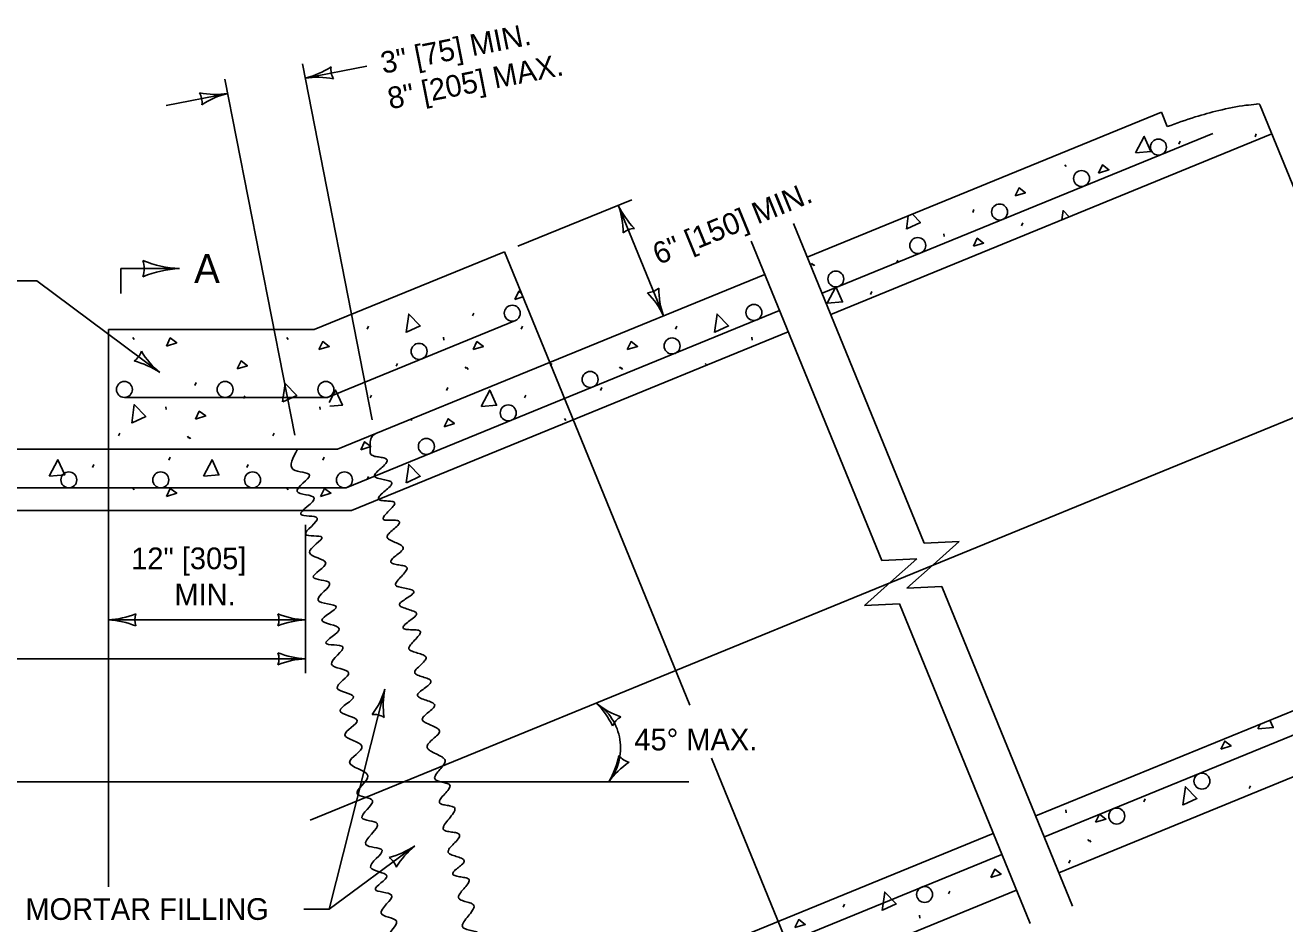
# Model space of a CAD drawing. Extents: x 49991.4 to 50021, y 49987.6 to 50011.4.
# Drawn here: x 50003.206 to 50006.69, y 50003.512 to 50005.996 of the extents above; entities that cross this region are included whole.
import ezdxf

# ---------------------------------------------------------------- set-up
doc = ezdxf.new("R2010")
doc.units = 0
for name, color, linetype in [('Level 1', 7, 'Continuous'), ('Level 2', 7, 'Continuous'), ('Level 3', 7, 'Continuous'), ('Level 4', 7, 'Continuous'), ('Level 5', 7, 'Continuous'), ('Level 6', 7, 'Continuous')]:
    doc.layers.add(name, color=color, linetype=linetype)

msp = doc.modelspace()

# ---------------------------------------------------------------- linework, layer by layer
at = {"layer": 'Level 1'}
for p, q in [((50006.6221, 50005.7743), (50007.2537, 50004.2304)), ((50005.3695, 50005.355), (50006.3487, 50005.7556)), ((50006.3487, 50005.7556), (50006.3651, 50005.7158)), ((50006.4914, 50005.6969), (50005.4104, 50005.255)), ((50005.4343, 50005.1964), (50006.6543, 50005.6955)), ((50006.3972, 50005.6675), (50006.4008, 50005.6755)), ((50006.6077, 50005.6879), (50006.6112, 50005.6959)), ((50006.0818, 50005.6106), (50006.0854, 50005.6053)), ((50005.827, 50005.4783), (50005.8305, 50005.4863)), ((50005.962, 50005.4419), (50005.9655, 50005.4499)), ((50005.7467, 50005.4196), (50005.7476, 50005.4116)), ((50004.0053, 50005.1544), (50004.5319, 50005.3698)), ((50004.5319, 50005.3698), (50004.6571, 50005.0636)), ((50005.3809, 50005.3379), (50005.3845, 50005.3326)), ((50005.3855, 50005.3359), (50005.3891, 50005.3305)), ((50005.6164, 50005.3389), (50005.6199, 50005.3469)), ((50004.0705, 50004.8236), (50005.2519, 50005.307)), ((50005.5445, 50005.2517), (50005.548, 50005.2596)), ((50005.2928, 50005.207), (50004.0941, 50004.7168)), ((50004.4434, 50005.1924), (50004.447, 50005.2004)), ((50003.4365, 50005.1544), (50003.4365, 50004.8236)), ((50003.4365, 50005.1544), (50004.0053, 50005.1544)), ((50004.562, 50005.1794), (50004.0422, 50004.9669)), ((50004.1091, 50004.6543), (50005.3168, 50005.1484)), ((50004.152, 50005.156), (50004.1556, 50005.164)), ((50004.5784, 50005.156), (50004.5819, 50005.164)), ((50005.0048, 50005.156), (50005.0083, 50005.164)), ((50003.5039, 50005.1323), (50003.5074, 50005.127)), ((50003.9303, 50005.1323), (50003.9338, 50005.127)), ((50004.3631, 50005.1337), (50004.364, 50005.1257)), ((50005.2159, 50005.1337), (50005.2168, 50005.1257)), ((50004.2328, 50005.053), (50004.2364, 50005.061)), ((50004.4237, 50005.052), (50004.4273, 50005.0467)), ((50004.4283, 50005.05), (50004.4319, 50005.0446)), ((50004.6592, 50005.053), (50004.6627, 50005.061)), ((50004.8501, 50005.052), (50004.8537, 50005.0467)), ((50004.8547, 50005.05), (50004.8582, 50005.0446)), ((50005.0876, 50005.0577), (50005.0891, 50005.061)), ((50003.6754, 50005), (50003.679, 50005.008)), ((50004.1609, 50004.9657), (50004.1644, 50004.9737)), ((50004.3713, 50004.9862), (50004.3749, 50004.9942)), ((50004.5873, 50004.9657), (50004.5908, 50004.9737)), ((50004.7977, 50004.9862), (50004.8013, 50004.9942)), ((50003.4807, 50004.9669), (50004.0422, 50004.9669)), ((50003.5951, 50004.9413), (50003.596, 50004.9333)), ((50003.8104, 50004.9636), (50003.8139, 50004.9716)), ((50004.0215, 50004.9413), (50004.0224, 50004.9333)), ((50004.2719, 50004.9089), (50004.2754, 50004.9036)), ((50004.6983, 50004.9089), (50004.7018, 50004.9036)), ((50003.4648, 50004.8606), (50003.4684, 50004.8686)), ((50003.8912, 50004.8606), (50003.8947, 50004.8686)), ((50003.6557, 50004.8596), (50003.6593, 50004.8543)), ((50003.6603, 50004.8576), (50003.6639, 50004.8522)), ((50002.7761, 50004.8236), (50004.0705, 50004.8236)), ((50003.6033, 50004.7938), (50003.6069, 50004.8018)), ((50004.0297, 50004.7938), (50004.0333, 50004.8018)), ((50003.3929, 50004.7733), (50003.3964, 50004.7813)), ((50003.8193, 50004.7733), (50003.8228, 50004.7813)), ((50004.152, 50004.7402), (50004.1556, 50004.7482)), ((50002.7761, 50004.7168), (50004.0941, 50004.7168)), ((50003.5039, 50004.7165), (50003.5074, 50004.7112)), ((50003.9303, 50004.7165), (50003.9338, 50004.7112)), ((50002.7761, 50004.6543), (50004.1091, 50004.6543)), ((50006.0014, 50003.8098), (50007.2216, 50004.3088)), ((50007.1297, 50004.2036), (50006.0252, 50003.7516)), ((50006.0656, 50003.6529), (50007.045, 50004.0536)), ((50006.5915, 50003.8854), (50006.595, 50003.8934)), ((50006.3001, 50003.849), (50006.3036, 50003.857)), ((50006.0848, 50003.8267), (50006.0857, 50003.8187)), ((50004.3994, 50003.1543), (50005.8839, 50003.7616)), ((50006.1454, 50003.745), (50006.149, 50003.7397)), ((50006.15, 50003.743), (50006.1536, 50003.7376)), ((50005.9077, 50003.7036), (50004.4541, 50003.109)), ((50006.093, 50003.6792), (50006.0966, 50003.6872)), ((50004.4328, 50002.985), (50005.9481, 50003.6048)), ((50005.7598, 50003.5942), (50005.7634, 50003.6022)), ((50005.4684, 50003.5578), (50005.472, 50003.5658)), ((50005.6796, 50003.5355), (50005.6804, 50003.5275))]:
    msp.add_line(p, q, dxfattribs=at)
for points in [[(50006.2773, 50005.6435), (50006.3013, 50005.6888), (50006.32, 50005.647), (50006.2782, 50005.6435)], [(50006.1751, 50005.5875), (50006.1857, 50005.6097), (50006.2035, 50005.5964), (50006.1751, 50005.5875)], [(50005.9444, 50005.5241), (50005.955, 50005.5463), (50005.9728, 50005.5329), (50005.9444, 50005.5241)], [(50005.6436, 50005.4327), (50005.6487, 50005.4692)], [(50005.66, 50005.4739), (50005.6825, 50005.4506), (50005.6444, 50005.433)], [(50006.0735, 50005.4579), (50006.077, 50005.4835), (50006.0938, 50005.4662)], [(50005.8288, 50005.3851), (50005.8394, 50005.4073), (50005.8572, 50005.394), (50005.8288, 50005.3851)], [(50004.5608, 50005.2382), (50004.5715, 50005.2604), (50004.5788, 50005.2548)], [(50005.4246, 50005.2277), (50005.4486, 50005.273), (50005.4672, 50005.2312), (50005.4255, 50005.2277)], [(50004.5829, 50005.245), (50004.5608, 50005.2382)], [(50004.26, 50005.1468), (50004.2671, 50005.1976), (50004.2989, 50005.1647), (50004.2609, 50005.1471)], [(50005.1128, 50005.1468), (50005.1198, 50005.1976), (50005.1516, 50005.1647), (50005.1136, 50005.1471)], [(50003.5971, 50005.1092), (50003.6078, 50005.1314), (50003.6255, 50005.1181), (50003.5971, 50005.1092)], [(50004.0188, 50005.0992), (50004.0295, 50005.1214), (50004.0472, 50005.1081), (50004.0188, 50005.0992)], [(50004.4452, 50005.0992), (50004.4558, 50005.1214), (50004.4736, 50005.1081), (50004.4452, 50005.0992)], [(50004.8716, 50005.0992), (50004.8822, 50005.1214), (50004.9, 50005.1081), (50004.8716, 50005.0992)], [(50003.7928, 50005.0458), (50003.8035, 50005.068), (50003.8212, 50005.0546), (50003.7928, 50005.0458)], [(50003.9184, 50004.9544), (50003.9255, 50005.0052), (50003.9573, 50004.9723), (50003.9192, 50004.9547)], [(50004.0471, 50004.9532), (50004.065, 50004.9871), (50004.0836, 50004.9453), (50004.0493, 50004.9424)], [(50004.4674, 50004.9418), (50004.4914, 50004.9871), (50004.51, 50004.9453), (50004.4683, 50004.9418)], [(50003.5011, 50004.8963), (50003.5082, 50004.9471), (50003.54, 50004.9142), (50003.502, 50004.8966)], [(50003.6772, 50004.9068), (50003.6878, 50004.929), (50003.7056, 50004.9157), (50003.6772, 50004.9068)], [(50004.3651, 50004.8858), (50004.3758, 50004.908), (50004.3935, 50004.8947), (50004.3651, 50004.8858)], [(50004.1344, 50004.8223), (50004.1451, 50004.8446), (50004.1628, 50004.8312), (50004.1344, 50004.8223)], [(50003.273, 50004.7494), (50003.297, 50004.7947), (50003.3156, 50004.7529), (50003.2739, 50004.7494)], [(50003.6994, 50004.7494), (50003.7234, 50004.7947), (50003.742, 50004.7529), (50003.7003, 50004.7494)], [(50004.26, 50004.731), (50004.2671, 50004.7818), (50004.2989, 50004.7489), (50004.2609, 50004.7313)], [(50003.5971, 50004.6934), (50003.6078, 50004.7156), (50003.6255, 50004.7023), (50003.5971, 50004.6934)], [(50004.0235, 50004.6934), (50004.0342, 50004.7156), (50004.0519, 50004.7023), (50004.0235, 50004.6934)], [(50006.6489, 50004.0746), (50006.6581, 50004.0541), (50006.6163, 50004.0506)], [(50006.6155, 50004.0506), (50006.6224, 50004.0637)], [(50006.5132, 50003.9946), (50006.5239, 50004.0168), (50006.5416, 50004.0035), (50006.5132, 50003.9946)], [(50006.4081, 50003.8398), (50006.4152, 50003.8906), (50006.447, 50003.8577), (50006.409, 50003.8401)], [(50006.1669, 50003.7922), (50006.1775, 50003.8144), (50006.1953, 50003.8011), (50006.1669, 50003.7922)], [(50005.8772, 50003.64), (50005.8879, 50003.6622), (50005.9056, 50003.6489), (50005.8772, 50003.64)], [(50005.5765, 50003.5486), (50005.5835, 50003.5994), (50005.6153, 50003.5665), (50005.5773, 50003.5489)], [(50005.3352, 50003.501), (50005.3459, 50003.5232), (50005.3636, 50003.5099), (50005.3352, 50003.501)]]:
    msp.add_lwpolyline(points, dxfattribs=at)
for centre in [(50006.3406, 50005.6592), (50006.1279, 50005.5723), (50005.9014, 50005.4797), (50005.6749, 50005.3871), (50005.4484, 50005.2945), (50004.5536, 50005.1999), (50005.2219, 50005.2019), (50004.2957, 50005.0944), (50004.9954, 50005.1093), (50003.4807, 50004.989), (50003.7593, 50004.989), (50004.0379, 50004.989), (50004.7689, 50005.0167), (50004.5424, 50004.9241), (50004.3159, 50004.8315), (50003.3271, 50004.7389), (50003.5812, 50004.7389), (50003.8353, 50004.7389), (50004.0894, 50004.7389), (50006.461, 50003.9061), (50006.2253, 50003.8096), (50005.694, 50003.5926)]:
    msp.add_circle(centre, 0.0221, dxfattribs=at)
for points in [[(50006.3651, 50005.7158), (50006.4424, 50005.7426), (50006.5078, 50005.7604), (50006.5827, 50005.7747), (50006.6118, 50005.778), (50006.6194, 50005.778), (50006.6207, 50005.777), (50006.6221, 50005.7743)], [(50004.173, 50004.8655), (50004.1642, 50004.8559), (50004.1602, 50004.8397), (50004.1602, 50004.8228), (50004.1622, 50004.8103), (50004.1697, 50004.8052), (50004.184, 50004.8024), (50004.1986, 50004.7996), (50004.204, 50004.7975), (50004.2071, 50004.7944), (50004.2035, 50004.7841), (50004.1908, 50004.7717), (50004.1776, 50004.7595), (50004.1736, 50004.7541), (50004.1728, 50004.7496), (50004.1755, 50004.7464), (50004.181, 50004.744), (50004.1965, 50004.7402), (50004.2121, 50004.7365), (50004.2176, 50004.7342), (50004.2193, 50004.7327), (50004.2203, 50004.7311), (50004.2204, 50004.729), (50004.2154, 50004.7211), (50004.2017, 50004.7087), (50004.1881, 50004.6962), (50004.1841, 50004.6908), (50004.1833, 50004.6862), (50004.1859, 50004.6836), (50004.191, 50004.6821), (50004.2057, 50004.6807), (50004.2203, 50004.6794), (50004.2256, 50004.678), (50004.2282, 50004.6757), (50004.2242, 50004.6661), (50004.2123, 50004.6533), (50004.2005, 50004.6404), (50004.197, 50004.635), (50004.1965, 50004.6308), (50004.1974, 50004.6296), (50004.2044, 50004.6277), (50004.2192, 50004.6275), (50004.2338, 50004.627), (50004.2389, 50004.6256), (50004.2405, 50004.6244), (50004.2414, 50004.6229), (50004.2406, 50004.6183), (50004.2369, 50004.6131), (50004.2244, 50004.6017), (50004.2118, 50004.5903), (50004.208, 50004.5852), (50004.2071, 50004.5807), (50004.208, 50004.5787), (50004.2148, 50004.5732), (50004.2296, 50004.5662), (50004.2443, 50004.5593), (50004.2494, 50004.5556), (50004.2519, 50004.5516), (50004.2471, 50004.5424), (50004.2346, 50004.5319), (50004.2222, 50004.5214), (50004.2184, 50004.5165), (50004.2176, 50004.5121), (50004.2201, 50004.5089), (50004.2252, 50004.5067), (50004.2399, 50004.5038), (50004.2547, 50004.5011), (50004.2599, 50004.499), (50004.2625, 50004.4962), (50004.2585, 50004.4857), (50004.2468, 50004.4723), (50004.235, 50004.459), (50004.2315, 50004.4533), (50004.2308, 50004.4487), (50004.2318, 50004.447), (50004.2394, 50004.4432), (50004.256, 50004.4397), (50004.2725, 50004.436), (50004.2782, 50004.4335), (50004.2801, 50004.432), (50004.281, 50004.4302), (50004.2799, 50004.4261), (50004.2756, 50004.4215), (50004.2614, 50004.4116), (50004.2471, 50004.4018), (50004.2427, 50004.3973), (50004.2414, 50004.3933), (50004.2439, 50004.3898), (50004.2493, 50004.3868), (50004.2651, 50004.3813), (50004.2809, 50004.3758), (50004.2864, 50004.3728), (50004.2889, 50004.3695), (50004.2836, 50004.3607), (50004.2701, 50004.35), (50004.2568, 50004.3391), (50004.2528, 50004.3342), (50004.2519, 50004.33), (50004.2546, 50004.3273), (50004.26, 50004.3257), (50004.2757, 50004.3247), (50004.2913, 50004.3237), (50004.2967, 50004.3221), (50004.2985, 50004.3209), (50004.2994, 50004.3194), (50004.2995, 50004.3172), (50004.2953, 50004.309), (50004.2835, 50004.2958), (50004.2717, 50004.2825), (50004.2683, 50004.2767), (50004.2678, 50004.2719), (50004.2688, 50004.27), (50004.2762, 50004.2654), (50004.2917, 50004.2603), (50004.3072, 50004.2551), (50004.3126, 50004.2519), (50004.3153, 50004.2481), (50004.3112, 50004.2383), (50004.2997, 50004.2268), (50004.288, 50004.2154), (50004.2844, 50004.2103), (50004.2836, 50004.2059), (50004.2861, 50004.2023), (50004.2912, 50004.1993), (50004.3061, 50004.1941), (50004.3209, 50004.1889), (50004.3261, 50004.1858), (50004.3285, 50004.1822), (50004.3284, 50004.18), (50004.3234, 50004.1728), (50004.3101, 50004.1623), (50004.2968, 50004.1519), (50004.2926, 50004.147), (50004.2915, 50004.1426), (50004.294, 50004.1388), (50004.2995, 50004.1354), (50004.3153, 50004.1296), (50004.3311, 50004.1236), (50004.3366, 50004.1202), (50004.339, 50004.1162), (50004.334, 50004.1069), (50004.3217, 50004.0965), (50004.3095, 50004.086), (50004.3057, 50004.0811), (50004.3047, 50004.0766), (50004.3073, 50004.0722), (50004.3128, 50004.0682), (50004.3286, 50004.0609), (50004.3443, 50004.0535), (50004.3497, 50004.0494), (50004.3522, 50004.0449), (50004.3472, 50004.0344), (50004.3348, 50004.0227), (50004.3225, 50004.0109), (50004.3187, 50004.0053), (50004.3179, 50004.0001), (50004.3189, 50003.9974), (50004.3265, 50003.9902), (50004.3428, 50003.9814), (50004.3593, 50003.9728), (50004.3651, 50003.9681), (50004.3681, 50003.9631), (50004.3643, 50003.9516), (50004.3534, 50003.9382), (50004.3425, 50003.9246), (50004.3394, 50003.9184), (50004.339, 50003.913), (50004.3399, 50003.9111), (50004.3463, 50003.907), (50004.3599, 50003.9033), (50004.3736, 50003.8999), (50004.3786, 50003.8976), (50004.3812, 50003.8945), (50004.3777, 50003.8839), (50004.3667, 50003.8708), (50004.3556, 50003.8577), (50004.3525, 50003.8519), (50004.3522, 50003.847), (50004.3532, 50003.8454), (50004.3597, 50003.8419), (50004.3733, 50003.839), (50004.3869, 50003.8362), (50004.3918, 50003.8341), (50004.3944, 50003.8312), (50004.3909, 50003.8184), (50004.3787, 50003.8021), (50004.3664, 50003.7859), (50004.363, 50003.7788), (50004.3628, 50003.7731), (50004.3638, 50003.7715), (50004.3708, 50003.768), (50004.3853, 50003.7654), (50004.3997, 50003.7627), (50004.4049, 50003.7605), (50004.4076, 50003.7573), (50004.4038, 50003.7464), (50004.3921, 50003.7333), (50004.3802, 50003.7204), (50004.3767, 50003.7146), (50004.376, 50003.7098), (50004.3769, 50003.708), (50004.3837, 50003.7032), (50004.3984, 50003.6979), (50004.4131, 50003.6926), (50004.4182, 50003.6895), (50004.4208, 50003.686), (50004.4165, 50003.6775), (50004.4049, 50003.6676), (50004.3933, 50003.6577), (50004.3899, 50003.6531), (50004.3892, 50003.6491), (50004.3918, 50003.646), (50004.397, 50003.6439), (50004.4116, 50003.6411), (50004.4262, 50003.6384), (50004.4314, 50003.6362), (50004.434, 50003.6332), (50004.4303, 50003.6222), (50004.4192, 50003.6084), (50004.4083, 50003.5945), (50004.4052, 50003.5883), (50004.405, 50003.5831), (50004.406, 50003.5813), (50004.4126, 50003.577), (50004.4261, 50003.5726), (50004.4397, 50003.5682), (50004.4446, 50003.5654), (50004.4472, 50003.562), (50004.4436, 50003.5489), (50004.4315, 50003.5328), (50004.4194, 50003.5169), (50004.4159, 50003.5098), (50004.4156, 50003.5039), (50004.4166, 50003.502), (50004.4239, 50003.4975), (50004.4393, 50003.4933), (50004.4547, 50003.4891), (50004.4602, 50003.4864), (50004.4631, 50003.4828), (50004.4593, 50003.4724), (50004.4476, 50003.46), (50004.4358, 50003.4478), (50004.4322, 50003.4424), (50004.4314, 50003.4379), (50004.434, 50003.4345), (50004.4395, 50003.4318), (50004.4552, 50003.4275), (50004.4709, 50003.423), (50004.4763, 50003.4203), (50004.4789, 50003.4168), (50004.4788, 50003.4148), (50004.4738, 50003.4081), (50004.4605, 50003.3983), (50004.4472, 50003.3885), (50004.443, 50003.384), (50004.4419, 50003.3799), (50004.4443, 50003.3764), (50004.4494, 50003.3733), (50004.4643, 50003.3678), (50004.4792, 50003.3624), (50004.4843, 50003.3594), (50004.4868, 50003.3561), (50004.482, 50003.3472), (50004.4694, 50003.3365), (50004.457, 50003.3256), (50004.4533, 50003.3207), (50004.4525, 50003.3165), (50004.4552, 50003.3137), (50004.4606, 50003.3121), (50004.4762, 50003.3111), (50004.4918, 50003.3101), (50004.4973, 50003.3086), (50004.4991, 50003.3075), (50004.5, 50003.306), (50004.5001, 50003.3038), (50004.4955, 50003.2956), (50004.4828, 50003.2823), (50004.4701, 50003.269), (50004.4663, 50003.2632), (50004.4657, 50003.2585), (50004.4666, 50003.2569), (50004.4735, 50003.2532), (50004.4882, 50003.2495), (50004.5029, 50003.2457), (50004.5081, 50003.2432), (50004.5106, 50003.24), (50004.506, 50003.2304), (50004.4933, 50003.219), (50004.4807, 50003.2075), (50004.477, 50003.2023), (50004.4763, 50003.1978), (50004.4772, 50003.1962), (50004.4836, 50003.1922), (50004.4973, 50003.1883), (50004.5111, 50003.1845), (50004.516, 50003.1822), (50004.5185, 50003.1793), (50004.5149, 50003.169), (50004.5038, 50003.1557), (50004.4928, 50003.1423), (50004.4898, 50003.1365), (50004.4895, 50003.1318), (50004.4904, 50003.1304), (50004.4969, 50003.128), (50004.5105, 50003.1274), (50004.5241, 50003.1269), (50004.529, 50003.1259), (50004.5317, 50003.1239), (50004.5281, 50003.114), (50004.5164, 50003.1004), (50004.5051, 50003.0866), (50004.5022, 50003.0809), (50004.5026, 50003.0764), (50004.5102, 50003.074), (50004.5228, 50003.0749), (50004.5352, 50003.0759), (50004.5397, 50003.0754), (50004.5422, 50003.0737), (50004.5449, 50003.0646), (50004.5463, 50003.0509), (50004.5391, 50003.0285)], [(50003.9597, 50004.8236), (50003.9479, 50004.7679), (50003.9928, 50004.752), (50003.9585, 50004.7072), (50004.006, 50004.6887), (50003.969, 50004.6438), (50004.0139, 50004.6333), (50003.9822, 50004.5884), (50004.0271, 50004.5805), (50003.9928, 50004.5383), (50004.0376, 50004.5092), (50004.0033, 50004.4697), (50004.0482, 50004.4538), (50004.0165, 50004.4063), (50004.0667, 50004.3878), (50004.0271, 50004.3509), (50004.0746, 50004.3271), (50004.0376, 50004.2876), (50004.0851, 50004.277), (50004.0535, 50004.2295), (50004.101, 50004.2057), (50004.0693, 50004.1635), (50004.1142, 50004.1398), (50004.0772, 50004.1002), (50004.1247, 50004.0738), (50004.0904, 50004.0342), (50004.1379, 50004.0025), (50004.1036, 50003.9577), (50004.1538, 50003.9207), (50004.1247, 50003.8706), (50004.1669, 50003.8521), (50004.1379, 50003.8046), (50004.1801, 50003.7888), (50004.1485, 50003.7307), (50004.1933, 50003.7149), (50004.1617, 50003.6674), (50004.2065, 50003.6436), (50004.1749, 50003.6067), (50004.2197, 50003.5908), (50004.1907, 50003.5407), (50004.2329, 50003.5196), (50004.2013, 50003.4615), (50004.2488, 50003.4404), (50004.2171, 50003.3955), (50004.2646, 50003.3744), (50004.2276, 50003.3375), (50004.2725, 50003.3137), (50004.2382, 50003.2741), (50004.2857, 50003.2636), (50004.2514, 50003.2161), (50004.2963, 50003.1976), (50004.262, 50003.1554), (50004.3042, 50003.1369), (50004.2752, 50003.0894), (50004.3174, 50003.0815), (50004.2883, 50003.034), (50004.3279, 50003.0313), (50004.3212, 50002.985)]]:
    msp.add_spline(points, degree=3, dxfattribs=at)
at = {"layer": 'Level 3'}
for p, q in [((50004.1664, 50004.9052), (50003.9732, 50005.8891)), ((50004.1511, 50005.8833), (50003.9809, 50005.8498)), ((50003.952, 50004.8629), (50003.7588, 50005.8469)), ((50003.7665, 50005.8076), (50003.5964, 50005.7741)), ((50004.5689, 50005.385), (50004.8838, 50005.5137)), ((50004.9719, 50005.1924), (50004.8468, 50005.4985)), ((50003.2384, 50005.2892), (50003.0974, 50005.2892)), ((50003.2384, 50005.2892), (50003.5788, 50005.0358)), ((50003.9815, 50004.6143), (50003.9815, 50004.2044)), ((50003.9815, 50004.352), (50003.4365, 50004.352)), ((50002.7488, 50004.2444), (50003.9815, 50004.2444)), ((50004.2013, 50004.1602), (50004.0474, 50003.5524)), ((50004.0474, 50003.5524), (50004.2839, 50003.7269)), ((50003.977, 50003.5524), (50004.0474, 50003.5524))]:
    msp.add_line(p, q, dxfattribs=at)
for centre, radius, start, end in [((50003.9247, 50006.0759), 0.233, 283.9639, 303.2137), ((50004.1067, 50005.8746), 0.0548, 173.2754, 208.9977), ((50004.0148, 50005.6301), 0.2223, 78.5926, 98.7761), ((50003.7326, 50006.0273), 0.2223, 258.598, 278.7815), ((50003.6407, 50005.7828), 0.0548, 353.2808, 29.0032), ((50003.8228, 50005.5815), 0.233, 103.9693, 123.2191), ((50004.6377, 50005.423), 0.2223, 359.6854, 19.8689), ((50005.0579, 50005.5972), 0.233, 205.0567, 224.3065), ((50004.8953, 50005.3798), 0.0548, 94.3682, 130.0905), ((50003.6457, 50005.6195), 0.2964, 247.456, 267.6395), ((50003.4625, 50005.3233), 0.073, 342.1388, 17.8612), ((50003.6488, 50005.013), 0.3107, 92.8273, 112.0772), ((50004.9234, 50005.3111), 0.0548, 274.3682, 310.0905), ((50004.7608, 50005.0937), 0.233, 25.0567, 44.3065), ((50005.181, 50005.268), 0.2223, 179.6854, 199.8689), ((50003.476, 50005.1124), 0.0548, 305.4741, 341.1965), ((50003.7188, 50005.2085), 0.2223, 210.7913, 230.9748), ((50003.4491, 50004.8423), 0.233, 56.1626, 75.4125), ((50003.425, 50004.5847), 0.233, 272.8273, 292.0772), ((50003.4273, 50004.1298), 0.2223, 67.456, 87.6395), ((50003.5647, 50004.352), 0.0548, 162.1388, 197.8612), ((50003.9907, 50004.5741), 0.2223, 247.456, 267.6395), ((50003.8533, 50004.352), 0.0548, 342.1388, 17.8612), ((50003.993, 50004.1193), 0.233, 92.8273, 112.0772), ((50003.9907, 50004.4665), 0.2223, 247.456, 267.6395), ((50003.8533, 50004.2444), 0.0548, 342.1388, 17.8612), ((50003.993, 50004.0117), 0.233, 92.8273, 112.0772), ((50003.9882, 50004.2236), 0.2223, 323.2469, 343.4304), ((50004.4297, 50004.1142), 0.233, 168.6182, 187.868), ((50004.705, 50003.9975), 0.1482, 321.0456, 57.0713), ((50004.631, 50003.962), 0.2223, 25.7888, 45.9723), ((50004.9317, 50004.3033), 0.233, 231.1601, 250.41), ((50004.1698, 50004.0359), 0.0548, 57.9297, 93.6521), ((50004.8813, 50004.0366), 0.0548, 120.4716, 156.194), ((50004.6204, 50004.0241), 0.233, 329.0527, 348.3025), ((50004.8915, 50004.0109), 0.0548, 218.3642, 254.0865), ((50004.9998, 50003.7732), 0.2223, 123.6814, 143.8649), ((50004.1594, 50003.9111), 0.2223, 283.8775, 304.061), ((50004.4313, 50003.5465), 0.233, 129.2488, 148.4987), ((50004.1807, 50003.6508), 0.0548, 18.5603, 54.2827)]:
    msp.add_arc(centre, radius, start, end, dxfattribs=at)
at = {"layer": 'Level 4'}
for p, q in [((50004.6571, 50005.0636), (50005.0446, 50004.1162)), ((50003.4365, 50004.8236), (50003.4365, 50003.6136)), ((50005.1047, 50003.9695), (50005.3533, 50003.3615))]:
    msp.add_line(p, q, dxfattribs=at)
at = {"layer": 'Level 5'}
msp.add_line((50007.1662, 50005.0957), (50003.9942, 50003.7981), dxfattribs=at)
msp.add_lwpolyline([(50001.7017, 50003.9043), (50005.0419, 50003.9043)], dxfattribs=at)
at = {"layer": 'Level 6'}
for p, q in [((50005.3316, 50005.4476), (50005.693, 50004.564)), ((50005.2141, 50005.3995), (50005.5755, 50004.5159)), ((50003.4705, 50005.3233), (50003.4705, 50005.2544)), ((50003.4705, 50005.3233), (50003.6335, 50005.3233)), ((50005.7898, 50004.5686), (50005.693, 50004.564)), ((50005.7898, 50004.5686), (50005.7175, 50004.504)), ((50005.6723, 50004.5205), (50005.5755, 50004.5159)), ((50005.6723, 50004.5205), (50005.6, 50004.4559)), ((50005.7175, 50004.504), (50005.6452, 50004.4394)), ((50005.6, 50004.4559), (50005.5277, 50004.3913)), ((50005.742, 50004.444), (50005.6452, 50004.4394)), ((50005.742, 50004.444), (50006.1034, 50003.5603)), ((50005.6245, 50004.3959), (50005.5277, 50004.3913)), ((50005.6245, 50004.3959), (50005.9859, 50003.5123))]:
    msp.add_line(p, q, dxfattribs=at)

# ---------------------------------------------------------------- texts
at = {"layer": 'Level 2'}
for s, rotation, p in [('3" [75] MIN.', 11.1476, (50004.1961, 50005.8616)), ('8" [205] MAX.', 11.1476, (50004.2155, 50005.7635)), ('6" [150] MIN.', 22.2532, (50004.9577, 50005.3328))]:
    msp.add_text(s, height=0.06, rotation=rotation, dxfattribs=at).set_placement(p)
for s, height, p in [('A', 0.08, (50003.6735, 50005.2833)), ('12" [305]', 0.06, (50003.4996, 50004.492)), ('MIN.', 0.06, (50003.6192, 50004.392)), ('45° MAX.', 0.06, (50004.8913, 50003.9909)), ('MORTAR FILLING', 0.06, (50003.207, 50003.5224))]:
    msp.add_text(s, height=height, dxfattribs=at).set_placement(p)

doc.saveas('drawing.dxf')
